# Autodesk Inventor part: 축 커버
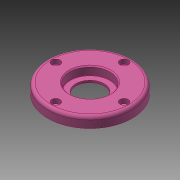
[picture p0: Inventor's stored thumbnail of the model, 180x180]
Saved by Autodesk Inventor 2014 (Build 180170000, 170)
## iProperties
Created: 2015-10
Part Number: 축 커버
Document SubType Name: Modeling
Designer: mdu
Density: 1 g/cm^3
Material: 강철, 연강
Appearance: 분홍색
Author: mdu
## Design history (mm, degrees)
sketch "스케치1"
  geometry: C1 r 40 at (0, 0) reference; C2 r 26 at (0, 0) reference; 1 further point
  node "참조1"
  node "참조2"
extrude "돌출1" new body sketch "스케치1" distance "d0" = 10; taper "d1" = 0 deg
extrude "돌출2" join sketch "스케치1" distance "d2" = 3; taper "d3" = 0 deg
hole "구멍1" diameter "d6" = 27; stored, may be unused: countersink angle "d10" = 90 deg, drill point angle "d12" = 118 deg; dims "d4" = 10, "d5" = 10, "d7" = 6, "d8" = 38, "d9" = 8, "d11" = 8
sketch "스케치2"
  geometry: C1 r 20 at (0, 0); 1 further point
  constraints: 1 centre point, 1 coincident
  dimensions: "d13" = 40 diameter of C1
extrude "돌출3" cut sketch "스케치2" distance "d14" = 3; taper "d15" = 0 deg
sketch "스케치3"
  geometry: C1 r 1.621 at (0, 32.5) reference; 1 further point
hole "구멍2" sketch "스케치3" at (0, 32.5) diameter "d16" = 4.5; stored, may be unused: countersink angle "d20" = 90 deg, drill point angle "d22" = 118 deg; dims "d17" = 6, "d18" = 8, "d19" = 4.4, "d21" = 8
fillet "모깎기1" dims "d26" = 3, "d27" = 0.3
chamfer "모따기1" distance "d28" = 1; stored, may be unused: second distance "d29" = 2, angle "d30" = 45 deg
node "솔리드1"
pattern_circular "원형 패턴1" dims angle "d24" = 360 deg
node "참조3"
